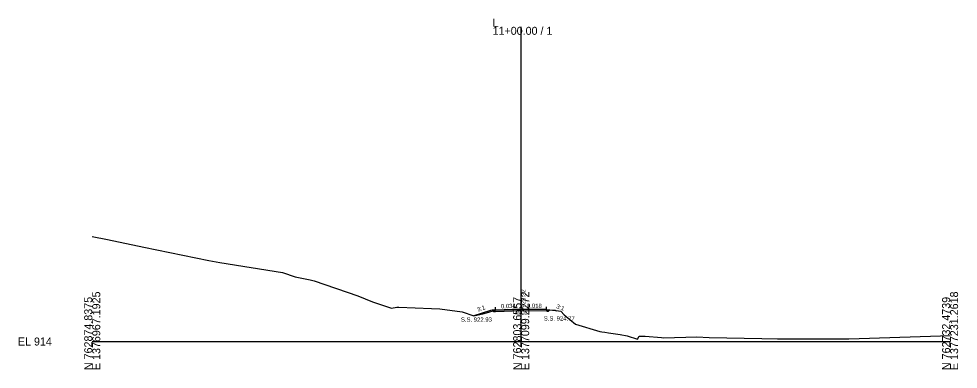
# Model space of a CAD drawing. Extents: x -26 to 303, y -10 to 6523.
# Drawn here: x -25.7 to 302.8, y 990.3 to 1112.9 of the extents above; entities that cross this region are included whole.
import ezdxf

# ---------------------------------------------------------------- set-up
doc = ezdxf.new("R2010")
doc.units = 0
for name, color, linetype in [('Exist Cross Section Cell', 7, 'Continuous'), ('Exist XS Center Line Elevation Label', 7, 'Continuous'), ('Exist XS Ground Line', 7, 'Continuous'), ('Prop XS Dump Level', 7, 'Continuous'), ('Prop XS Elevation Labels', 7, 'Continuous'), ('Prop XS EOT Tick Mark', 7, 'Continuous'), ('Prop XS Finish Grade', 7, 'Continuous'), ('Prop XS Finish Grade Earthwork', 7, 'Continuous'), ('Prop XS Finish Grade Pavement', 7, 'Continuous'), ('Prop XS Pvmt Edge Slope', 7, 'Continuous'), ('Prop XS SE Text', 7, 'Continuous'), ('Prop XS Side Slope Text', 7, 'Continuous'), ('Prop XS SS Elevation Text', 7, 'Continuous'), ('Prop XS Subgrade Earthwork', 7, 'Continuous')]:
    doc.layers.add(name, color=color, linetype=linetype)

msp = doc.modelspace()

# ---------------------------------------------------------------- linework, layer by layer
at = {"layer": 'Exist Cross Section Cell'}
for p, q in [((150, 1000), (150, 1110.06)), ((0, 1000), (150, 1000)), ((150, 1000), (300, 1000))]:
    msp.add_line(p, q, dxfattribs=at)
at = {"layer": 'Exist XS Ground Line'}
for p, q in [((0, 1036.69), (5.34, 1035.68)), ((5.34, 1035.68), (18.05, 1032.94)), ((18.05, 1032.94), (40.79, 1028.33)), ((40.79, 1028.33), (44.57, 1027.59)), ((44.57, 1027.59), (66.55, 1024.11)), ((66.55, 1024.11), (70.95, 1022.56)), ((70.95, 1022.56), (76.19, 1021.61)), ((76.19, 1021.61), (77.55, 1021.25)), ((77.55, 1021.25), (92.83, 1016)), ((92.83, 1016), (98.05, 1013.86)), ((98.05, 1013.86), (104.6, 1011.67)), ((104.6, 1011.67), (106.55, 1011.97)), ((106.55, 1011.97), (107.27, 1012)), ((107.27, 1012), (118.62, 1011.51)), ((118.62, 1011.51), (121.54, 1011.45)), ((121.54, 1011.45), (129.41, 1010.34)), ((129.41, 1010.34), (133.43, 1008.93)), ((133.43, 1008.93), (137.08, 1009.82)), ((137.08, 1009.82), (141.03, 1011.01)), ((141.03, 1011.01), (145.87, 1011.16)), ((145.87, 1011.16), (149.98, 1011.32)), ((149.98, 1011.32), (154.82, 1011.25)), ((154.82, 1011.25), (158.91, 1011.16)), ((158.91, 1011.16), (163.07, 1010.68)), ((163.07, 1010.68), (163.86, 1010.61)), ((163.86, 1010.61), (165.05, 1009.31)), ((165.05, 1009.31), (169.01, 1006.02)), ((169.01, 1006.02), (177.55, 1003.51)), ((177.55, 1003.51), (178.24, 1003.37)), ((178.24, 1003.37), (179.25, 1003.22)), ((179.25, 1003.22), (180.59, 1003.04)), ((180.59, 1003.04), (184.57, 1002.45)), ((184.57, 1002.45), (187.07, 1001.98)), ((296.65, 1002.02), (300, 1002.12)), ((187.07, 1001.98), (190.65, 1000.85)), ((190.65, 1000.85), (191.29, 1001.82)), ((191.29, 1001.82), (192.13, 1001.83)), ((192.13, 1001.83), (192.52, 1001.82)), ((192.52, 1001.82), (193.32, 1001.86)), ((193.32, 1001.86), (199.06, 1001.42)), ((199.06, 1001.42), (199.83, 1001.28)), ((199.83, 1001.28), (211.44, 1001.63)), ((211.44, 1001.63), (215.74, 1001.45)), ((215.74, 1001.45), (234.22, 1001.07)), ((234.22, 1001.07), (239.67, 1000.97)), ((239.67, 1000.97), (243.84, 1000.94)), ((243.84, 1000.94), (261.74, 1000.96)), ((261.74, 1000.96), (264.55, 1000.94)), ((264.55, 1000.94), (271.79, 1001.19)), ((271.79, 1001.19), (296.65, 1002.02))]:
    msp.add_line(p, q, dxfattribs=at)
at = {"layer": 'Prop XS Dump Level'}
for p, q in [((150, 1011.32), (141.03, 1011.01)), ((158.92, 1011.16), (150, 1011.32))]:
    msp.add_line(p, q, dxfattribs=at)
at = {"layer": 'Prop XS EOT Tick Mark'}
for p, q in [((141.03, 1011.01), (141.03, 1012.01)), ((158.91, 1011.16), (158.91, 1012.16))]:
    msp.add_line(p, q, dxfattribs=at)
at = {"layer": 'Prop XS Finish Grade'}
for p, q in [((141.03, 1011.01), (139.9, 1010.92)), ((158.91, 1011.16), (160.02, 1011.07))]:
    msp.add_line(p, q, dxfattribs=at)
at = {"layer": 'Prop XS Finish Grade Earthwork'}
for p, q in [((139.25, 1010.87), (133.43, 1008.93)), ((139.9, 1010.92), (139.25, 1010.87)), ((160.02, 1011.07), (161.91, 1010.92)), ((161.91, 1010.92), (162.35, 1010.77))]:
    msp.add_line(p, q, dxfattribs=at)
at = {"layer": 'Prop XS Finish Grade Pavement'}
for p, q in [((141.03, 1011.01), (150, 1011.32)), ((150, 1011.32), (158.92, 1011.16))]:
    msp.add_line(p, q, dxfattribs=at)
at = {"layer": 'Prop XS Pvmt Edge Slope'}
for p, q in [((141.03, 1011.01), (140.42, 1010.41)), ((158.91, 1011.16), (159.51, 1010.57))]:
    msp.add_line(p, q, dxfattribs=at)
at = {"layer": 'Prop XS Subgrade Earthwork'}
for p, q in [((140.42, 1010.41), (139.9, 1010.92)), ((141.03, 1010.43), (140.42, 1010.41)), ((150, 1010.73), (141.03, 1010.43)), ((158.92, 1010.58), (150, 1010.73)), ((158.92, 1010.58), (159.51, 1010.57)), ((159.51, 1010.57), (160.02, 1011.07))]:
    msp.add_line(p, q, dxfattribs=at)

# ---------------------------------------------------------------- texts
at = {"layer": 'Exist Cross Section Cell'}
for s, p in [('L', (140, 1110.06)), ('11+00.00 / 1', (140, 1107.26)), ('EL 914', (-26, 998.6))]:
    msp.add_text(s, height=2.8, dxfattribs=at).set_placement(p)
for s, p in [('N 762874.8375', (0, 990)), ('E 1376967.1925', (2.8, 990)), ('N 762803.6557', (150, 990)), ('E 1377099.2272', (152.8, 990)), ('N 762732.4739', (300, 990)), ('E 1377231.2618', (302.8, 990))]:
    msp.add_text(s, height=2.8, rotation=90, dxfattribs=at).set_placement(p)
at = {"layer": 'Exist XS Center Line Elevation Label'}
msp.add_text('925.32', height=0.998, dxfattribs=at).set_placement((147.84, 1009.42))
at = {"layer": 'Prop XS Dump Level'}
msp.add_text('Case1', height=0.04, dxfattribs=at).set_placement((161.91, 1010.88))
at = {"layer": 'Prop XS Elevation Labels'}
msp.add_text(' 925.32', height=1.5, rotation=90, dxfattribs=at).set_placement((151.5, 1011.32))
at = {"layer": 'Prop XS SE Text'}
for s, rotation, p in [('0.034', 1.945, (142.93, 1011.58)), ('0.018', 358.9932, (152.01, 1011.78))]:
    msp.add_text(s, height=1.5, rotation=rotation, dxfattribs=at).set_placement(p)
at = {"layer": 'Prop XS Side Slope Text'}
for rotation, p in [(18.4349, (134.85, 1010.41)), (341.5651, (162.14, 1011.66))]:
    msp.add_text('3:1', height=1.5, rotation=rotation, dxfattribs=at).set_placement(p)
at = {"layer": 'Prop XS SS Elevation Text'}
for s, p in [('S.S. 924.77', (157.91, 1007.32)), ('S.S. 922.93', (128.93, 1006.92))]:
    msp.add_text(s, height=1.5, dxfattribs=at).set_placement(p)

doc.saveas('drawing.dxf')
